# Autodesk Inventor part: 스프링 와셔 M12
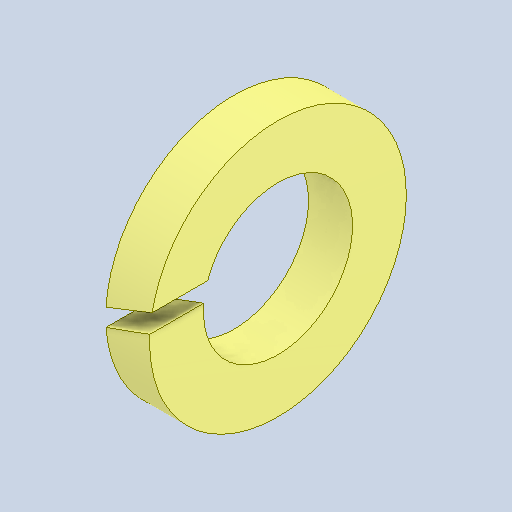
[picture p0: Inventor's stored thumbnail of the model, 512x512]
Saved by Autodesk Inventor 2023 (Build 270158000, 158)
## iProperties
Created: 2026-06
Part Number: 스프링 와셔 M12
Material: 강철, 연강
Description: 스프링 잠금 와셔
Document SubType Name: Modeling
Designer: 4강의실
Density: 7.85 g/cm^3
Appearance: 기본값
Author: jhkim
Sending System: Autodesk Inventor 2027
Preprocessor: ST-DEVELOPER v20.1
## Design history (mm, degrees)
feature "Solid1"
node "솔리드1"
